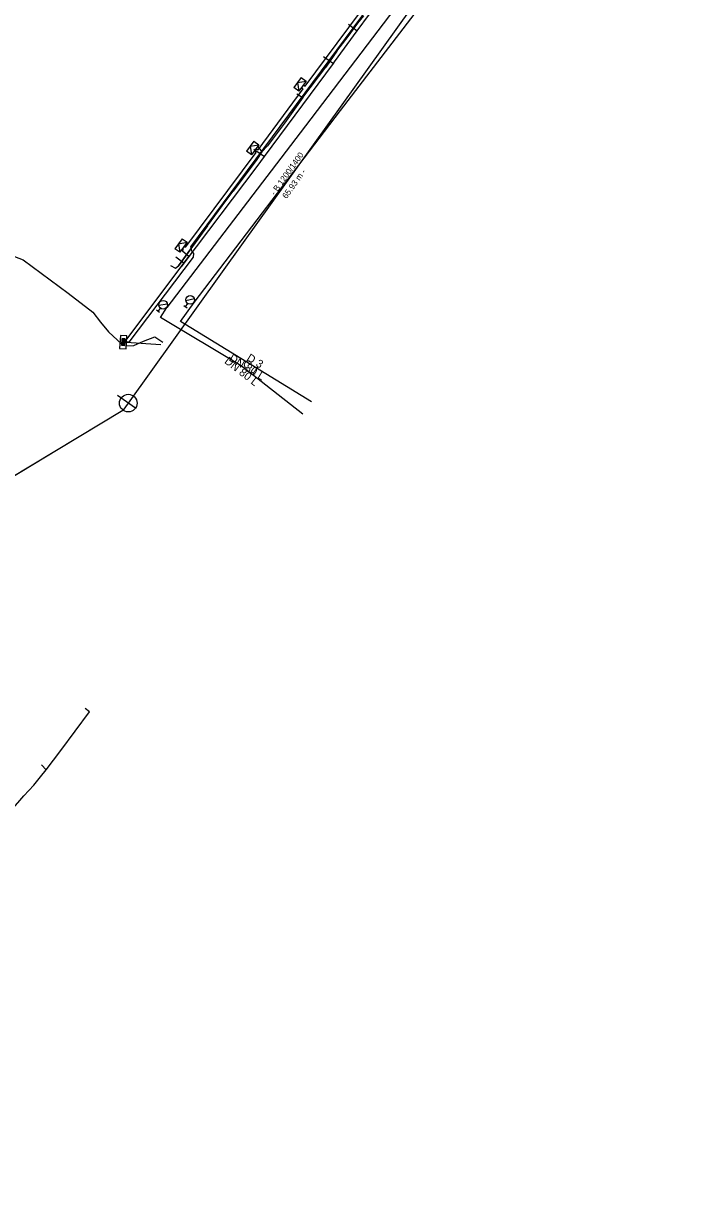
# Model space of a CAD drawing. Extents: x -600636 to -600148, y -1203980 to -1203569.
# Drawn here: x -600313.9 to -600236.9, y -1203908.1 to -1203773.6 of the extents above; entities that cross this region are included whole.
import ezdxf

# ---------------------------------------------------------------- set-up
doc = ezdxf.new("R2010")
doc.units = 0
for name, color, linetype in [('Cetin zam průběh', 7, 'Continuous'), ('EON objekty', 7, 'Continuous'), ('EON podzemní NN', 7, 'Continuous'), ('EON podzemní zrušené', 7, 'Continuous'), ('GasNet NTL', 7, 'Continuous'), ('Implicitní', 7, 'Continuous'), ('VaK Břeclav_kanalizace', 7, 'Continuous'), ('VaK Břeclav_kanalizace_popis', 7, 'Continuous'), ('Vak Břeclav_vodovod', 7, 'Continuous'), ('Vak Břeclav_vodovod_popis', 7, 'Continuous'), ('Vrstva 9', 7, 'Continuous')]:
    doc.layers.add(name, color=color, linetype=linetype)

# ---------------------------------------------------------------- blocks, each defined once
blk = doc.blocks.new('NN630')
at = {"layer": 'Vrstva 9'}
for points in [[(0, -0.7), (-0.7, 0)], [(-0.7, -0.7), (-0.7, 0), (0.7, 0), (0.7, -0.7)], [(-0.7, -0.7), (0.7, -0.7)], [(0, -0.7), (0.7, 0)]]:
    blk.add_lwpolyline(points, dxfattribs=at)
blk = doc.blocks.new('NN620')
at = {"layer": 'EON objekty'}
for points in [[(0.75, 0), (-0.75, 0)], [(-0.75, 0), (-0.75, -0.75)], [(0.75, -0.75), (0.75, 0)], [(-0.75, -0.75), (0.75, -0.75)], [(0.37, -0.18), (-0.38, -0.18)], [(-0.38, -0.18), (-0.38, -0.56)], [(-0.38, -0.56), (0.37, -0.56)], [(0.32, -0.23), (-0.33, -0.23)], [(-0.33, -0.23), (-0.33, -0.51)], [(-0.33, -0.51), (0.32, -0.51)], [(0.27, -0.27), (-0.28, -0.27)], [(-0.28, -0.27), (-0.28, -0.46)], [(-0.28, -0.46), (0.27, -0.46)], [(0.23, -0.32), (-0.23, -0.32)], [(-0.23, -0.32), (-0.23, -0.42)], [(-0.23, -0.42), (0.23, -0.42)], [(-0.19, -0.37), (0.19, -0.37)], [(0.23, -0.42), (0.23, -0.32)], [(0.27, -0.46), (0.27, -0.27)], [(0.32, -0.51), (0.32, -0.23)], [(0.37, -0.56), (0.37, -0.18)]]:
    blk.add_lwpolyline(points, dxfattribs=at)
blk = doc.blocks.new('MoSymbol 2')
at = {"layer": 'Implicitní'}
blk.add_line((0, 0.0005), (0, -0.00075), dxfattribs=at)
blk.add_circle((0, 0), 0.0005, dxfattribs=at)
blk = doc.blocks.new('MoSymbol 3')
at = {"layer": 'Implicitní'}
for p, q in [((-0.000365, -0.000365), (0.000365, 0.000365)), ((-0.000225, 0.00095), (0.000225, 0.00095)), ((0, 0.00095), (0, 0.0005))]:
    blk.add_line(p, q, dxfattribs=at)
blk.add_circle((0, 0), 0.0005, dxfattribs=at)

msp = doc.modelspace()

# ---------------------------------------------------------------- linework, layer by layer
at = {"layer": 'Cetin zam průběh'}
for points in [[(-600277, -1203775.03), (-600275.93, -1203773.51), (-600275.25, -1203772.7)], [(-600282.15, -1203781.98), (-600279.54, -1203778.52), (-600278.29, -1203776.71), (-600277, -1203775.03)], [(-600278.29, -1203776.71), (-600279.54, -1203778.52)], [(-600282.15, -1203781.98), (-600284.25, -1203784.89), (-600286.19, -1203787.47), (-600286.81, -1203788.15)], [(-600282.15, -1203781.98), (-600284.25, -1203784.89)], [(-600282.84, -1203781.57), (-600282.15, -1203781.98)], [(-600286.19, -1203787.47), (-600286.81, -1203788.15), (-600287.41, -1203789.01)], [(-600287.27, -1203787.53), (-600286.81, -1203788.15)], [(-600297.22, -1203801.09), (-600296.62, -1203801.37), (-600296.31, -1203801.11), (-600293.01, -1203796.55), (-600291.33, -1203794.31), (-600290.09, -1203792.64), (-600287.41, -1203789.01), (-600286.81, -1203788.15)], [(-600287.41, -1203789.01), (-600290.09, -1203792.64)], [(-600293.01, -1203796.55), (-600296.31, -1203801.11)], [(-600311.34, -1203858.41), (-600309.66, -1203856.2), (-600306.41, -1203851.81), (-600306.9, -1203851.44)], [(-600319.59, -1203867.6), (-600318.11, -1203866.27), (-600313.88, -1203861.36), (-600312.73, -1203860.16), (-600311.97, -1203859.2), (-600311.34, -1203858.41)], [(-600311.87, -1203857.86), (-600311.34, -1203858.41)], [(-600312.73, -1203860.16), (-600313.88, -1203861.36)]]:
    msp.add_lwpolyline(points, dxfattribs=at)
at = {"layer": 'EON podzemní NN'}
for points in [[(-600241.11, -1203718.3), (-600241.96, -1203719.12), (-600246.21, -1203724.8), (-600246.44, -1203725.59), (-600245.07, -1203727.73), (-600245.15, -1203730.41), (-600245.18, -1203733.27), (-600246.2, -1203734.47), (-600259.05, -1203754.79), (-600265.34, -1203759.06), (-600294.93, -1203798.94), (-600294.8, -1203799.42), (-600294.6, -1203799.71), (-600294.64, -1203800.12), (-600301.93, -1203809.79), (-600302.19, -1203809.81)], [(-600302.16, -1203809.41), (-600302.14, -1203809.41), (-600295.1, -1203800.06), (-600295.79, -1203799.48), (-600295.73, -1203799.01), (-600295.45, -1203798.97), (-600287.48, -1203788.23), (-600287.57, -1203788.17), (-600287.57, -1203787.92), (-600287.34, -1203787.85), (-600287.25, -1203787.91), (-600282.12, -1203781.01), (-600282.23, -1203780.94), (-600282.21, -1203780.7), (-600282, -1203780.61), (-600281.89, -1203780.69), (-600273.29, -1203769.11)], [(-600302.21, -1203810.21), (-600301.35, -1203810.16), (-600300.26, -1203809.69), (-600299, -1203809.18), (-600298.07, -1203809.78)]]:
    msp.add_lwpolyline(points, dxfattribs=at)
at = {"layer": 'EON podzemní zrušené'}
msp.add_lwpolyline([(-600321.04, -1203798.12), (-600320.34, -1203797.17), (-600319.55, -1203796.91), (-600318.77, -1203796.92), (-600318.15, -1203797.61), (-600316.82, -1203799.33), (-600313.94, -1203800.43), (-600308.84, -1203804.22), (-600306.03, -1203806.39), (-600305.15, -1203807.51), (-600304.25, -1203808.61), (-600302.72, -1203810.01), (-600302.23, -1203809.81), (-600298.29, -1203810.07)], dxfattribs=at)
at = {"layer": 'GasNet NTL'}
for points in [[(-600295.95, -1203801.21), (-600295.65, -1203800.81), (-600287.36, -1203789.82), (-600286.53, -1203788.7), (-600278.7, -1203778.11), (-600278.55, -1203777.91), (-600275.98, -1203774.4), (-600270.38, -1203766.79), (-600268.42, -1203764.21), (-600266.21, -1203761.3), (-600264.99, -1203760.1), (-600261.02, -1203756.81), (-600258.4, -1203754.89), (-600252.86, -1203745.77), (-600247.26, -1203737.18), (-600244.78, -1203732.86), (-600245.17, -1203730.96), (-600245.99, -1203727.04), (-600245.48, -1203726.22)], [(-600276.99, -1203773.66), (-600275.98, -1203774.4)], [(-600279.8, -1203777.31), (-600278.7, -1203778.11)], [(-600287.72, -1203787.87), (-600286.53, -1203788.7)], [(-600296.59, -1203800.11), (-600295.65, -1203800.81)]]:
    msp.add_lwpolyline(points, dxfattribs=at)
at = {"layer": 'VaK Břeclav_kanalizace'}
for points in [[(-600263.65, -1203763.1), (-600288.95, -1203798.48), (-600302, -1203816.72)], [(-600302, -1203816.72), (-600302.6, -1203817.56), (-600309.96, -1203822), (-600326.02, -1203831.69), (-600331.32, -1203836.69), (-600343.36, -1203848.04), (-600352.1, -1203856.28), (-600362.57, -1203868.11), (-600368.81, -1203875.94), (-600393.33, -1203906.69), (-600394.49, -1203908.15)], [(-600302, -1203816.72), (-600302.02, -1203816.73), (-600302.61, -1203817.55), (-600326.03, -1203831.65), (-600352.13, -1203856.23), (-600362.65, -1203868.03), (-600394.48, -1203908.11), (-600394.49, -1203908.15)]]:
    msp.add_lwpolyline(points, dxfattribs=at)
at = {"layer": 'Vak Břeclav_vodovod'}
for points in [[(-600237.02, -1203720.96), (-600247.04, -1203738.76), (-600258.19, -1203754.2), (-600265.44, -1203763.56), (-600282.47, -1203785.99), (-600297.62, -1203805.86)], [(-600294.52, -1203805.29), (-600277.89, -1203783.47), (-600269.03, -1203771.91), (-600239.86, -1203732.74), (-600236.89, -1203728.36)], [(-600282.15, -1203817.96), (-600289.19, -1203812.47), (-600298.34, -1203807), (-600297.62, -1203805.86)], [(-600281.18, -1203816.56), (-600296.07, -1203807.44), (-600294.52, -1203805.29)]]:
    msp.add_lwpolyline(points, dxfattribs=at)

# ---------------------------------------------------------------- block references
at = {"layer": 'EON podzemní NN'}
for name, p, rotation in [('NN630', (-600282.21, -1203780.7), -126.74925827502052), ('NN630', (-600287.57, -1203787.92), -126.45685548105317), ('NN630', (-600295.73, -1203799.01), -125.7817332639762), ('NN620', (-600302.19, -1203809.81), -93.05850273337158)]:
    msp.add_blockref(name, p, dxfattribs=dict(at, rotation=rotation))
at = {"layer": 'VaK Břeclav_kanalizace', "xscale": 1999.750031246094, "yscale": 1999.7500312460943, "rotation": -125.57555543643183}
msp.add_blockref('MoSymbol 2', (-600302, -1203816.72), dxfattribs=at)
at = {"layer": 'Vak Břeclav_vodovod', "xscale": 999.875015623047}
for p, yscale, rotation in [((-600298.04, -1203805.54), 999.875015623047, 142.3596414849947), ((-600294.97, -1203804.99), 999.8750156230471, 146.8693287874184)]:
    msp.add_blockref('MoSymbol 3', p, dxfattribs=dict(at, yscale=yscale, rotation=rotation))

# ---------------------------------------------------------------- texts
at = {"layer": 'VaK Břeclav_kanalizace_popis'}
for s, height, p in [('- B 1200/1400', 0.6824, (-600285.36, -1203793.17)), ('65.93 m -', 0.682, (-600284.01, -1203793.54))]:
    msp.add_text(s, height=height, rotation=54.4244, dxfattribs=at).set_placement(p)
at = {"layer": 'Vak Břeclav_vodovod_popis'}
for s, rotation, p in [('DN 80 L', 322.0653, (-600291.15, -1203812.1)), ('DN 80 L', 328.5023, (-600290.62, -1203811.84)), ('D 3', 328.5023, (-600288.63, -1203811.82)), ('C 1', 322.0653, (-600289.08, -1203812.38))]:
    msp.add_text(s, height=0.91, rotation=rotation, dxfattribs=at).set_placement(p)

doc.saveas('drawing.dxf')
